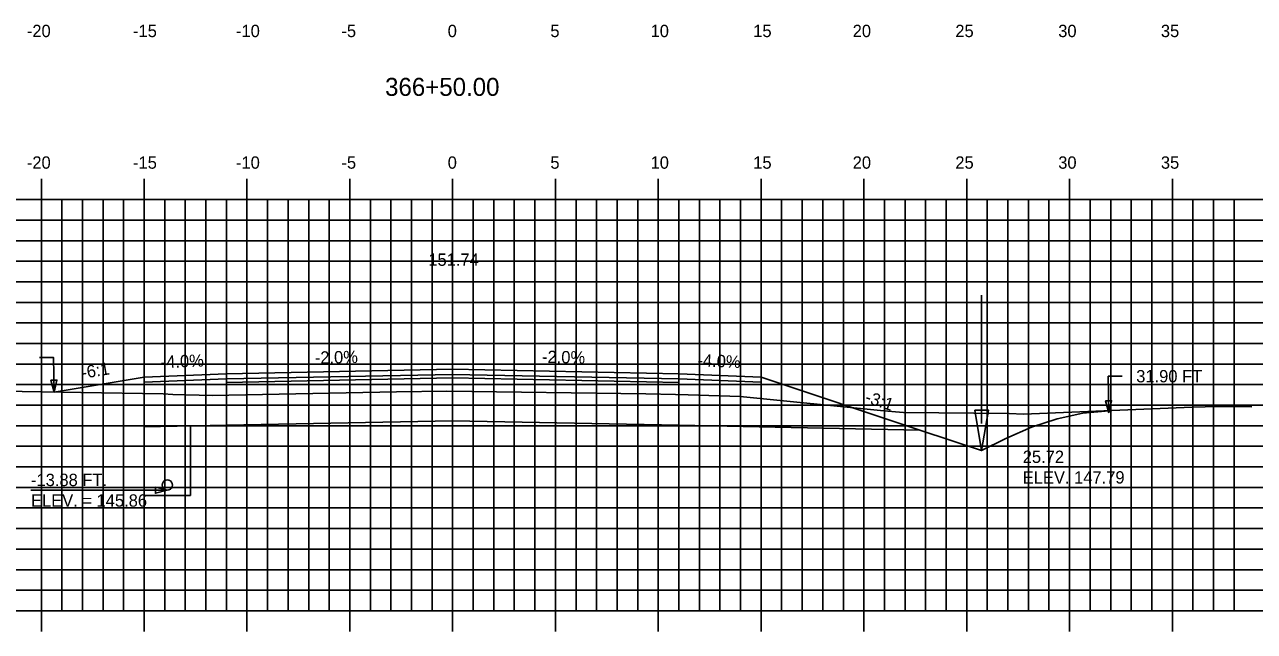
# Model space of a CAD drawing. Extents: x 1147412 to 1147582, y 608981 to 609091.
# Drawn here: x 1147473.9 to 1147533.7, y 609019.3 to 609048.8 of the extents above; entities that cross this region are included whole.
import ezdxf

# ---------------------------------------------------------------- set-up
doc = ezdxf.new("R2010")
doc.units = 0
for name, color, linetype in [('ANNOTATION', 7, 'Continuous'), ('D_Drainage_Ditch_Line', 7, 'Continuous'), ('D_Drainage_Underdrain', 7, 'Continuous'), ('D_Drainage_Underdrain_06in', 7, 'Continuous'), ('D_Roadway_Centerline', 7, 'Continuous'), ('D_Roadway_Centerline_Text', 7, 'Continuous'), ('D_Roadway_Edge_Shoulder', 7, 'Continuous'), ('D_Roadway_Edge_TW', 7, 'Continuous'), ('D_Roadway_Pavement', 7, 'Continuous'), ('D_Roadway_SlopeLines', 7, 'Continuous'), ('D_Roadway_SubGrade', 7, 'Continuous'), ('D_Text_Standard', 7, 'Continuous'), ('H_V ANNOTATION', 7, 'Continuous'), ('MAJOR', 7, 'Continuous'), ('MINOR', 7, 'Continuous'), ('S_Roadway_Centerline', 7, 'Continuous')]:
    doc.layers.add(name, color=color, linetype=linetype)

msp = doc.modelspace()

# ---------------------------------------------------------------- linework, layer by layer
msp.add_lwpolyline([(1147475.322, 609030.971), (1147479.696, 609031.7), (1147479.697, 609031.7), (1147483.697, 609031.86), (1147494.697, 609032.08), (1147505.697, 609031.86), (1147509.697, 609031.7), (1147517.421, 609029.125), (1147520.421, 609028.125), (1147521.6, 609028.715), (1147522.85, 609029.268), (1147524.1, 609029.678), (1147525.35, 609029.945), (1147526.6, 609030.068)])
at = {"layer": 'D_Drainage_Ditch_Line'}
msp.add_line((1147520.421, 609029.438), (1147520.421, 609035.681), dxfattribs=at)
msp.add_lwpolyline([(1147520.093, 609030.094), (1147520.749, 609030.094), (1147520.421, 609028.125)], close=True, dxfattribs=at)
at = {"layer": 'D_Drainage_Underdrain'}
msp.add_lwpolyline([(1147479.697, 609029.28), (1147479.697, 609025.95), (1147481.947, 609025.95), (1147481.947, 609029.325)], close=True, dxfattribs=at)
at = {"layer": 'D_Drainage_Underdrain_06in'}
msp.add_lwpolyline([(1147480.822, 609026.7), (1147480.9, 609026.688), (1147480.969, 609026.652), (1147481.025, 609026.597), (1147481.06, 609026.527), (1147481.072, 609026.45), (1147481.06, 609026.373), (1147481.025, 609026.303), (1147480.969, 609026.248), (1147480.9, 609026.212), (1147480.822, 609026.2), (1147480.745, 609026.212), (1147480.675, 609026.248), (1147480.62, 609026.303), (1147480.585, 609026.373), (1147480.572, 609026.45), (1147480.585, 609026.527), (1147480.62, 609026.597), (1147480.675, 609026.652), (1147480.745, 609026.688)], close=True, dxfattribs=at)
at = {"layer": 'D_Roadway_Edge_Shoulder'}
for points in [[(1147483.697, 609031.86), (1147479.697, 609031.7), (1147479.697, 609031.45), (1147483.697, 609031.61)], [(1147505.697, 609031.86), (1147509.697, 609031.7), (1147509.697, 609031.45), (1147505.697, 609031.61)]]:
    msp.add_lwpolyline(points, close=True, dxfattribs=at)
at = {"layer": 'D_Roadway_Edge_TW'}
msp.add_lwpolyline([(1147483.697, 609031.61), (1147483.697, 609031.86), (1147494.697, 609032.08), (1147505.697, 609031.86), (1147505.697, 609031.61), (1147494.697, 609031.83)], close=True, dxfattribs=at)
at = {"layer": 'D_Roadway_Pavement'}
msp.add_lwpolyline([(1147483.697, 609031.443), (1147483.697, 609031.61), (1147494.697, 609031.83), (1147505.697, 609031.61), (1147505.697, 609031.443), (1147494.697, 609031.663)], close=True, dxfattribs=at)
at = {"layer": 'D_Roadway_SlopeLines'}
for points in [[(1147479.697, 609031.7), (1147475.322, 609030.971)], [(1147520.421, 609028.125), (1147521.6, 609028.715), (1147522.85, 609029.268), (1147524.1, 609029.678), (1147525.35, 609029.945), (1147526.6, 609030.068)], [(1147517.421, 609029.125), (1147520.421, 609028.125)]]:
    msp.add_lwpolyline(points, dxfattribs=at)
at = {"layer": 'D_Roadway_SubGrade'}
for points in [[(1147483.697, 609031.443), (1147483.697, 609031.61), (1147479.697, 609031.45), (1147479.697, 609031.7), (1147479.696, 609031.7), (1147479.697, 609029.28), (1147483.697, 609029.36)], [(1147483.697, 609029.36), (1147483.697, 609031.443), (1147494.697, 609031.663), (1147505.697, 609031.443), (1147505.697, 609029.36), (1147494.697, 609029.58)], [(1147505.697, 609031.443), (1147505.697, 609031.61), (1147509.697, 609031.45), (1147509.697, 609031.7), (1147509.698, 609031.7), (1147517.421, 609029.125), (1147505.697, 609029.36)]]:
    msp.add_lwpolyline(points, close=True, dxfattribs=at)
at = {"layer": 'D_Text_Standard'}
msp.add_line((1147474.193, 609026.2), (1147478.607, 609026.2), dxfattribs=at)
for points in [[(1147475.322, 609030.971), (1147475.288, 609032.648), (1147474.608, 609032.648)], [(1147526.6, 609029.965), (1147526.579, 609031.745), (1147527.259, 609031.745)], [(1147480.822, 609026.2), (1147479.287, 609026.2), (1147478.607, 609026.2)]]:
    msp.add_lwpolyline(points, dxfattribs=at)
for points in [[(1147475.322, 609030.971), (1147475.165, 609031.55), (1147475.456, 609031.556)], [(1147526.6, 609029.965), (1147526.447, 609030.545), (1147526.738, 609030.549)], [(1147480.822, 609026.2), (1147480.24, 609026.054), (1147480.24, 609026.345)]]:
    msp.add_lwpolyline(points, close=True, dxfattribs=at)
at = {"layer": 'MAJOR'}
for p, q in [((1147474.697, 609041.337), (1147474.697, 609040.335)), ((1147479.697, 609041.337), (1147479.697, 609040.335)), ((1147484.697, 609041.337), (1147484.697, 609040.335)), ((1147489.697, 609041.337), (1147489.697, 609040.335)), ((1147494.697, 609041.337), (1147494.697, 609040.335)), ((1147499.697, 609041.337), (1147499.697, 609040.335)), ((1147504.697, 609041.337), (1147504.697, 609040.335)), ((1147509.697, 609041.337), (1147509.697, 609040.335)), ((1147514.697, 609041.337), (1147514.697, 609040.335)), ((1147519.697, 609041.337), (1147519.697, 609040.335)), ((1147524.697, 609041.337), (1147524.697, 609040.335)), ((1147529.697, 609041.337), (1147529.697, 609040.335)), ((1147424.697, 609040.335), (1147564.697, 609040.335)), ((1147424.697, 609040.335), (1147564.697, 609040.335)), ((1147474.697, 609020.335), (1147474.697, 609040.335)), ((1147479.697, 609020.335), (1147479.697, 609040.335)), ((1147484.697, 609020.335), (1147484.697, 609040.335)), ((1147489.697, 609020.335), (1147489.697, 609040.335)), ((1147494.697, 609020.335), (1147494.697, 609040.335)), ((1147499.697, 609020.335), (1147499.697, 609040.335)), ((1147504.697, 609020.335), (1147504.697, 609040.335)), ((1147509.697, 609020.335), (1147509.697, 609040.335)), ((1147514.697, 609020.335), (1147514.697, 609040.335)), ((1147519.697, 609020.335), (1147519.697, 609040.335)), ((1147524.697, 609020.335), (1147524.697, 609040.335)), ((1147529.697, 609020.335), (1147529.697, 609040.335)), ((1147424.697, 609035.335), (1147564.697, 609035.335)), ((1147424.697, 609030.335), (1147564.697, 609030.335)), ((1147424.697, 609025.335), (1147564.697, 609025.335)), ((1147424.697, 609020.335), (1147564.697, 609020.335)), ((1147424.697, 609020.335), (1147564.697, 609020.335)), ((1147474.697, 609019.333), (1147474.697, 609020.335)), ((1147479.697, 609019.333), (1147479.697, 609020.335)), ((1147484.697, 609019.333), (1147484.697, 609020.335)), ((1147489.697, 609019.333), (1147489.697, 609020.335)), ((1147494.697, 609019.333), (1147494.697, 609020.335)), ((1147499.697, 609019.333), (1147499.697, 609020.335)), ((1147504.697, 609019.333), (1147504.697, 609020.335)), ((1147509.697, 609019.333), (1147509.697, 609020.335)), ((1147514.697, 609019.333), (1147514.697, 609020.335)), ((1147519.697, 609019.333), (1147519.697, 609020.335)), ((1147524.697, 609019.333), (1147524.697, 609020.335)), ((1147529.697, 609019.333), (1147529.697, 609020.335))]:
    msp.add_line(p, q, dxfattribs=at)
at = {"layer": 'MINOR'}
for p, q in [((1147475.697, 609020.335), (1147475.697, 609040.335)), ((1147476.697, 609020.335), (1147476.697, 609040.335)), ((1147477.697, 609020.335), (1147477.697, 609040.335)), ((1147478.697, 609020.335), (1147478.697, 609040.335)), ((1147480.697, 609020.335), (1147480.697, 609040.335)), ((1147481.697, 609020.335), (1147481.697, 609040.335)), ((1147482.697, 609020.335), (1147482.697, 609040.335)), ((1147483.697, 609020.335), (1147483.697, 609040.335)), ((1147485.697, 609020.335), (1147485.697, 609040.335)), ((1147486.697, 609020.335), (1147486.697, 609040.335)), ((1147487.697, 609020.335), (1147487.697, 609040.335)), ((1147488.697, 609020.335), (1147488.697, 609040.335)), ((1147490.697, 609020.335), (1147490.697, 609040.335)), ((1147491.697, 609020.335), (1147491.697, 609040.335)), ((1147492.697, 609020.335), (1147492.697, 609040.335)), ((1147493.697, 609020.335), (1147493.697, 609040.335)), ((1147495.697, 609020.335), (1147495.697, 609040.335)), ((1147496.697, 609020.335), (1147496.697, 609040.335)), ((1147497.697, 609020.335), (1147497.697, 609040.335)), ((1147498.697, 609020.335), (1147498.697, 609040.335)), ((1147500.697, 609020.335), (1147500.697, 609040.335)), ((1147501.697, 609020.335), (1147501.697, 609040.335)), ((1147502.697, 609020.335), (1147502.697, 609040.335)), ((1147503.697, 609020.335), (1147503.697, 609040.335)), ((1147505.697, 609020.335), (1147505.697, 609040.335)), ((1147506.697, 609020.335), (1147506.697, 609040.335)), ((1147507.697, 609020.335), (1147507.697, 609040.335)), ((1147508.697, 609020.335), (1147508.697, 609040.335)), ((1147510.697, 609020.335), (1147510.697, 609040.335)), ((1147511.697, 609020.335), (1147511.697, 609040.335)), ((1147512.697, 609020.335), (1147512.697, 609040.335)), ((1147513.697, 609020.335), (1147513.697, 609040.335)), ((1147515.697, 609020.335), (1147515.697, 609040.335)), ((1147516.697, 609020.335), (1147516.697, 609040.335)), ((1147517.697, 609020.335), (1147517.697, 609040.335)), ((1147518.697, 609020.335), (1147518.697, 609040.335)), ((1147520.697, 609020.335), (1147520.697, 609040.335)), ((1147521.697, 609020.335), (1147521.697, 609040.335)), ((1147522.697, 609020.335), (1147522.697, 609040.335)), ((1147523.697, 609020.335), (1147523.697, 609040.335)), ((1147525.697, 609020.335), (1147525.697, 609040.335)), ((1147526.697, 609020.335), (1147526.697, 609040.335)), ((1147527.697, 609020.335), (1147527.697, 609040.335)), ((1147528.697, 609020.335), (1147528.697, 609040.335)), ((1147530.697, 609020.335), (1147530.697, 609040.335)), ((1147531.697, 609020.335), (1147531.697, 609040.335)), ((1147532.697, 609020.335), (1147532.697, 609040.335)), ((1147424.697, 609039.335), (1147564.697, 609039.335)), ((1147424.697, 609038.335), (1147564.697, 609038.335)), ((1147424.697, 609037.335), (1147564.697, 609037.335)), ((1147424.697, 609036.335), (1147564.697, 609036.335)), ((1147424.697, 609034.335), (1147564.697, 609034.335)), ((1147424.697, 609033.335), (1147564.697, 609033.335)), ((1147424.697, 609032.335), (1147564.697, 609032.335)), ((1147424.697, 609031.335), (1147564.697, 609031.335)), ((1147424.697, 609029.335), (1147564.697, 609029.335)), ((1147424.697, 609028.335), (1147564.697, 609028.335)), ((1147424.697, 609027.335), (1147564.697, 609027.335)), ((1147424.697, 609026.335), (1147564.697, 609026.335)), ((1147424.697, 609024.335), (1147564.697, 609024.335)), ((1147424.697, 609023.335), (1147564.697, 609023.335)), ((1147424.697, 609022.335), (1147564.697, 609022.335)), ((1147424.697, 609021.335), (1147564.697, 609021.335))]:
    msp.add_line(p, q, dxfattribs=at)
at = {"layer": 'S_Roadway_Centerline'}
msp.add_lwpolyline([(1147467.093, 609031.118), (1147476.613, 609030.948), (1147480.619, 609030.883), (1147481.083, 609030.855), (1147482.998, 609030.8), (1147491.966, 609030.979), (1147494.419, 609031.023), (1147504.094, 609030.893), (1147505.532, 609030.859), (1147506.148, 609030.836), (1147508.675, 609030.75), (1147515.669, 609030.056), (1147516.623, 609029.974), (1147521.759, 609029.93), (1147522.451, 609029.897), (1147530.656, 609030.235), (1147531.294, 609030.255), (1147531.793, 609030.277), (1147533.56, 609030.251)], dxfattribs=at)

# ---------------------------------------------------------------- texts
at = {"layer": 'ANNOTATION'}
for s, rotation, p in [('-4.0%', 2.29061, (1147480.513, 609032.133)), ('-2.0%', 1.14576, (1147488, 609032.346)), ('-2.0%', 358.85424, (1147499.04, 609032.393)), ('-4.0%', 357.70939, (1147506.593, 609032.225)), ('-6:1', 9.46422, (1147476.689, 609031.612)), ('-3:1', 341.56521, (1147514.709, 609030.484))]:
    msp.add_text(s, height=0.6, rotation=rotation, dxfattribs=at).set_placement(p)
at = {"layer": 'D_Roadway_Centerline'}
for s, p in [('C', (1147494.692, 609032.08)), ('L', (1147494.697, 609032.073))]:
    msp.add_text(s, height=0.0146, dxfattribs=at).set_placement(p)
at = {"layer": 'D_Roadway_Centerline_Text'}
msp.add_text('151.74', height=0.6, dxfattribs=at).set_placement((1147493.515, 609037.112))
at = {"layer": 'D_Text_Standard'}
for s, p in [('31.90 FT', (1147527.939, 609031.445)), ('25.72', (1147522.421, 609027.525)), ('-13.88 FT.', (1147474.193, 609026.4)), ('ELEV. 147.79', (1147522.421, 609026.523)), ('ELEV. = 145.86', (1147474.193, 609025.4))]:
    msp.add_text(s, height=0.6, dxfattribs=at).set_placement(p)
at = {"layer": 'H_V ANNOTATION'}
for s, height, p in [('-20', 0.6, (1147473.991, 609048.235)), ('-15', 0.6, (1147479.154, 609048.235)), ('-10', 0.6, (1147484.162, 609048.235)), ('-5', 0.6, (1147489.288, 609048.235)), ('0', 0.6, (1147494.457, 609048.235)), ('5', 0.6, (1147499.449, 609048.235)), ('10', 0.6, (1147504.323, 609048.235)), ('15', 0.6, (1147509.315, 609048.235)), ('20', 0.6, (1147514.151, 609048.235)), ('25', 0.6, (1147519.143, 609048.235)), ('30', 0.6, (1147524.146, 609048.235)), ('35', 0.6, (1147529.138, 609048.235)), ('366+50.00', 0.875, (1147491.412, 609045.378)), ('-20', 0.6, (1147473.991, 609041.835)), ('-15', 0.6, (1147479.154, 609041.835)), ('-10', 0.6, (1147484.162, 609041.835)), ('-5', 0.6, (1147489.288, 609041.835)), ('0', 0.6, (1147494.457, 609041.835)), ('5', 0.6, (1147499.449, 609041.835)), ('10', 0.6, (1147504.323, 609041.835)), ('15', 0.6, (1147509.315, 609041.835)), ('20', 0.6, (1147514.151, 609041.835)), ('25', 0.6, (1147519.143, 609041.835)), ('30', 0.6, (1147524.146, 609041.835)), ('35', 0.6, (1147529.138, 609041.835))]:
    msp.add_text(s, height=height, dxfattribs=at).set_placement(p)
at = {"layer": 'S_Roadway_Centerline'}
for s, p in [('L', (1147494.41, 609031.016)), ('C', (1147494.413, 609031.023))]:
    msp.add_text(s, height=0.0146, dxfattribs=at).set_placement(p)

doc.saveas('drawing.dxf')
